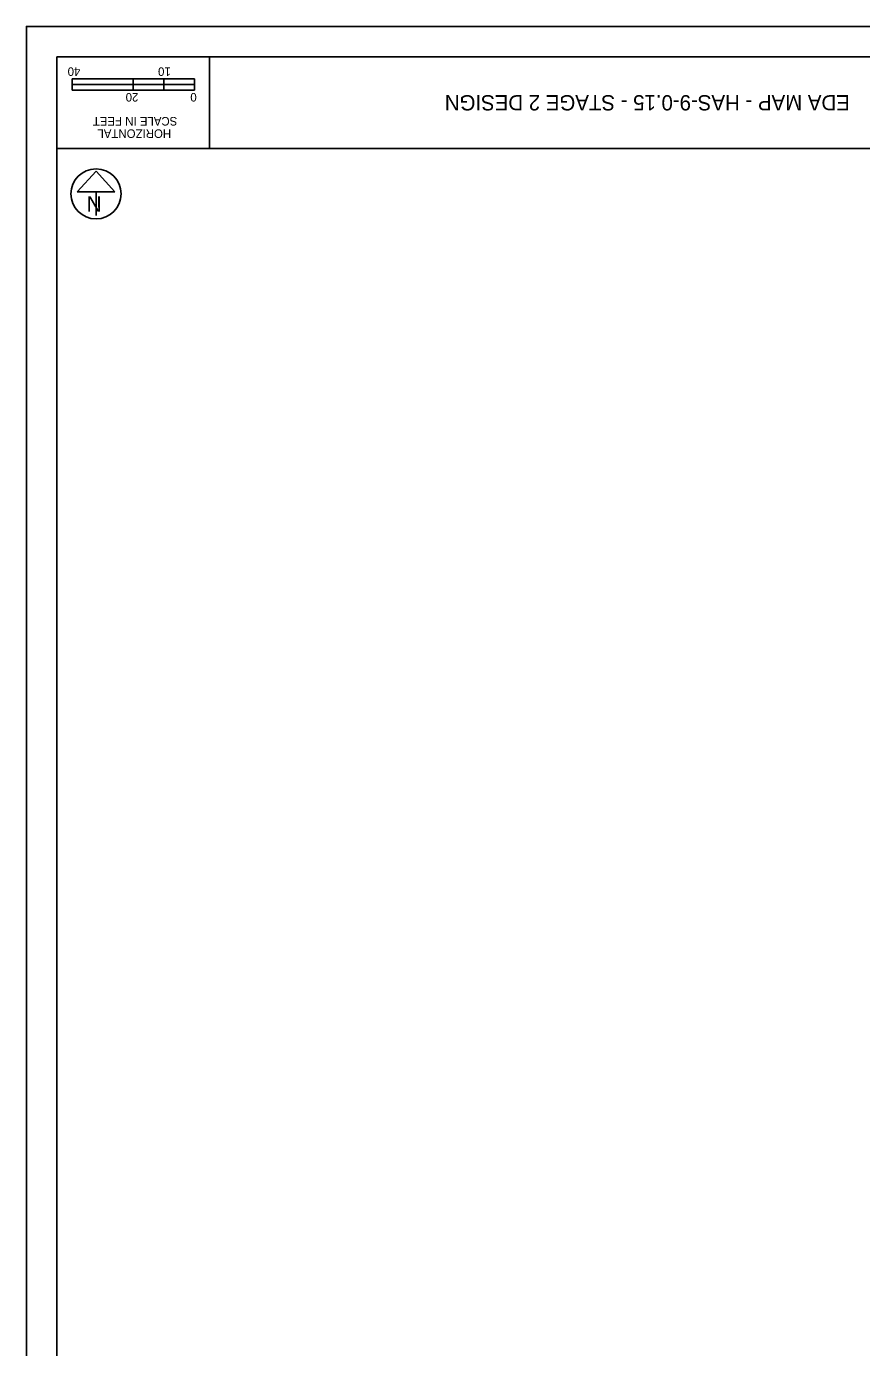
# Model space of a CAD drawing. Extents: x 2392589 to 2394670, y 184794 to 185659.
# Drawn here: x 2392589.3 to 2392862.8, y 185226.6 to 185659.2 of the extents above; entities that cross this region are included whole.
import ezdxf

# ---------------------------------------------------------------- set-up
doc = ezdxf.new("R2010")
doc.units = 0
for name, color, linetype in [('MD_P_Surface_Aggregate_Base', 7, 'Continuous'), ('MD_P_Surface_Asphalt_Concrete_Base', 7, 'Continuous'), ('MD_P_Surface_Asphalt_Concrete_Intermediate_Course', 7, 'Continuous'), ('MD_P_Surface_Asphalt_Concrete_Surface_Course', 7, 'Continuous'), ('MD_P_Surface_Finished_Grade_Seeded', 7, 'Continuous')]:
    doc.layers.add(name, color=color, linetype=linetype)

msp = doc.modelspace()

# ---------------------------------------------------------------- linework, layer by layer
at = {"layer": 'MD_P_Surface_Aggregate_Base'}
for p, q in [((2392612.08, 185611.82), (2392605.93, 185604.99)), ((2392618.23, 185604.99), (2392612.08, 185611.82)), ((2392605.93, 185604.99), (2392618.23, 185604.99)), ((2392612.08, 185604.99), (2392612.08, 185597.26))]:
    msp.add_line(p, q, dxfattribs=at)
msp.add_circle((2392612.08, 185604.34), 8.2, dxfattribs=at)
at = {"layer": 'MD_P_Surface_Asphalt_Concrete_Base'}
msp.add_circle((2392612.08, 185604.34), 8.2, dxfattribs=at)
at = {"layer": 'MD_P_Surface_Asphalt_Concrete_Intermediate_Course'}
msp.add_lwpolyline([(2393029.28, 184979.17), (2393029.28, 185659.17), (2392589.28, 185659.17), (2392589.28, 184979.17)], close=True, dxfattribs=at)
at = {"layer": 'MD_P_Surface_Asphalt_Concrete_Surface_Course'}
for p, q in [((2392604.28, 185642.06), (2392644.28, 185642.06)), ((2392604.28, 185642.06), (2392604.28, 185638.31)), ((2392604.28, 185640.19), (2392624.28, 185640.19)), ((2392604.28, 185640.17), (2392604.28, 185640.19)), ((2392604.28, 185638.31), (2392604.28, 185640.17)), ((2392634.28, 185642.04), (2392624.28, 185642.04)), ((2392624.28, 185642.04), (2392624.28, 185640.17)), ((2392624.28, 185640.19), (2392624.28, 185638.31)), ((2392624.28, 185640.17), (2392634.28, 185640.17)), ((2392634.28, 185640.17), (2392634.28, 185642.04)), ((2392644.28, 185640.17), (2392634.28, 185640.17)), ((2392634.28, 185640.17), (2392634.28, 185638.31)), ((2392644.28, 185642.06), (2392644.28, 185638.31)), ((2392644.28, 185638.31), (2392644.28, 185640.17)), ((2392644.28, 185638.31), (2392604.28, 185638.31)), ((2392624.28, 185638.31), (2392604.28, 185638.31)), ((2392634.28, 185638.31), (2392644.28, 185638.31))]:
    msp.add_line(p, q, dxfattribs=at)
at = {"layer": 'MD_P_Surface_Finished_Grade_Seeded'}
for p, q in [((2392649.28, 185619.17), (2392649.28, 185649.17)), ((2393019.28, 185619.17), (2392599.28, 185619.17))]:
    msp.add_line(p, q, dxfattribs=at)
msp.add_lwpolyline([(2392599.28, 185009.17), (2392599.28, 185649.17), (2393019.28, 185649.17), (2393019.28, 185009.17)], close=True, dxfattribs=at)

# ---------------------------------------------------------------- texts
at = {"layer": 'MD_P_Surface_Aggregate_Base'}
msp.add_text('N', height=5, dxfattribs=at).set_placement((2392609.05, 185598.52))
at = {"layer": 'MD_P_Surface_Asphalt_Concrete_Surface_Course'}
for s, height, p in [('40', 2.8, (2392606.95, 185645.78)), ('10', 2.8, (2392636.55, 185645.78)), ('20', 2.8, (2392625.95, 185637.38)), ('0', 2.8, (2392645.05, 185637.38)), ('EDA MAP - HAS-9-0.15 - STAGE 2 DESIGN', 5, (2392858.96, 185636.67)), ('SCALE IN FEET', 2.8, (2392638.7, 185629.52)), ('HORIZONTAL', 2.8, (2392636.67, 185625.47))]:
    msp.add_text(s, height=height, rotation=180, dxfattribs=at).set_placement(p)

doc.saveas('drawing.dxf')
